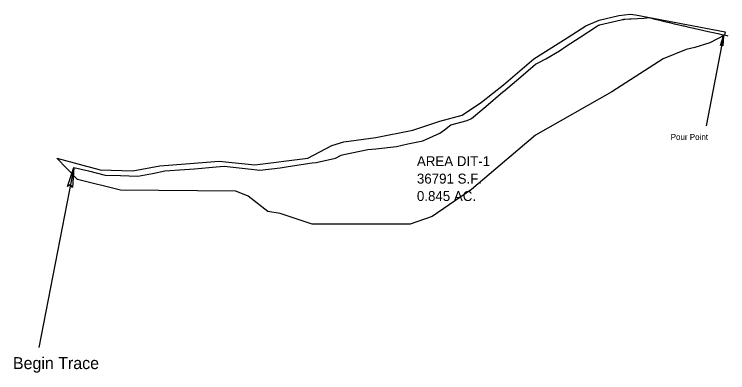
# Model space of a CAD drawing. Extents: x 2773 to 5445, y 2717 to 3371.
import ezdxf

# ---------------------------------------------------------------- set-up
doc = ezdxf.new("R2010")
doc.units = 0
for name, color, linetype in [('Default', 7, 'Continuous'), ('DESIGN - SCRATCH - User 1', 7, 'Continuous'), ('SURVEY - CENTERLINE - Preliminary', 7, 'Continuous'), ('SURVEY - CENTERLINE - Preliminary Text', 7, 'Continuous'), ('SURVEY - DRAINAGE - Area Shapes', 7, 'Continuous')]:
    doc.layers.add(name, color=color, linetype=linetype)

msp = doc.modelspace()

# ---------------------------------------------------------------- linework, layer by layer
at = {"layer": 'DESIGN - SCRATCH - User 1'}
msp.add_line((3485.62, 3055.04), (3468.09, 2964.59), dxfattribs=at)
msp.add_lwpolyline([(3485.62, 3055.04), (3484.94, 3044.93), (3483.96, 3046.45), (3482.43, 3045.42)], close=True, dxfattribs=at)
msp.add_lwpolyline([(3485.62, 3055.04), (3484.94, 3044.93), (3483.96, 3046.45), (3482.43, 3045.42), (3485.62, 3055.04)], dxfattribs=at)
at = {"layer": 'SURVEY - CENTERLINE - Preliminary'}
msp.add_lwpolyline([(2832.45, 2922.94), (2847.47, 2919.39), (2864.12, 2915.09), (2879.54, 2914.67), (2897.07, 2914.19), (2911.62, 2916.79), (2923.98, 2919.53), (2943.7, 2920.94), (2954, 2921.66), (2975.77, 2923.4), (2983.69, 2924.13), (3007.85, 2921.56), (3019.5, 2920.26), (3039.93, 2922.51), (3047.96, 2924), (3072.01, 2927.46), (3076.15, 2928.03), (3095.68, 2932.32), (3101.29, 2935.2), (3104.08, 2936.04), (3127.95, 2940.82), (3136.16, 2941.67), (3156.99, 2943.95), (3168.24, 2946.59), (3183.5, 2949.72), (3200.31, 2957.37), (3205.01, 2960.65), (3211.67, 2965.51), (3228.11, 2969.93), (3232.39, 2972.04), (3246.55, 2984.04), (3263.83, 2998.69), (3264.21, 2998.96), (3264.47, 2999.15), (3281.86, 3013.89), (3296.54, 3026.47), (3300.1, 3028.21), (3306.96, 3031.88), (3320.74, 3040.03), (3328.62, 3045.44), (3340.44, 3052.84), (3359.01, 3065.07), (3360.01, 3065.56), (3360.12, 3065.6), (3360.17, 3065.62), (3360.25, 3065.64), (3360.4, 3065.7), (3360.57, 3065.75), (3360.7, 3065.79), (3360.78, 3065.82), (3360.8, 3065.82), (3361.06, 3065.89), (3382.86, 3070.98), (3384.05, 3071.26), (3385.06, 3071.46), (3385.52, 3071.55), (3386.45, 3071.61), (3391.06, 3071.91), (3392.78, 3072.02), (3405.45, 3072.83), (3407.45, 3072.97), (3408.47, 3073.05), (3408.53, 3073.1), (3408.53, 3073.1), (3408.54, 3073.11), (3408.79, 3073.22), (3408.84, 3073.27), (3409.89, 3073.25), (3409.92, 3073.26), (3411.8, 3072.89), (3416.67, 3071.74), (3421.55, 3070.6), (3424.85, 3069.83), (3426.42, 3069.46), (3431.1, 3068.37), (3431.29, 3068.32), (3436.16, 3067.18), (3441.04, 3066.03), (3445.15, 3065.07), (3445.91, 3064.89), (3450.78, 3063.76), (3455.66, 3062.63), (3456.93, 3062.35), (3460.27, 3061.61), (3470.31, 3059.38), (3475.19, 3058.28), (3480.07, 3057.19), (3484.95, 3056.09), (3486.24, 3055.83), (3489.01, 3055.29), (3489.86, 3055.12)], dxfattribs=at)
at = {"layer": 'SURVEY - CENTERLINE - Preliminary Text'}
msp.add_line((2832.45, 2922.94), (2797.38, 2742.04), dxfattribs=at)
msp.add_lwpolyline([(2832.45, 2922.94), (2831.08, 2902.73), (2829.12, 2905.76), (2826.07, 2903.7)], close=True, dxfattribs=at)
msp.add_lwpolyline([(2832.45, 2922.94), (2831.08, 2902.73), (2829.12, 2905.76), (2826.07, 2903.7), (2832.45, 2922.94)], dxfattribs=at)
at = {"layer": 'SURVEY - DRAINAGE - Area Shapes'}
for points in [[(3328.62, 3053.06), (3347.21, 3065.07), (3360.7, 3070.87), (3380.24, 3075.46), (3391.7, 3076.61), (3397.13, 3076.03), (3487.12, 3058.96)], [(3487.12, 3058.96), (3486.62, 3055.76), (3471.95, 3048.08), (3456.93, 3043.22), (3448, 3041.12), (3424.81, 3031.88), (3373.51, 2998.69), (3296.54, 2955.27), (3232.39, 2900.73), (3192.87, 2873.65), (3170.72, 2865.94), (3072.01, 2865.94), (3039.93, 2876.62), (3027.7, 2878.6), (3007.85, 2894.22), (2995.32, 2899.13)], [(2815.39, 2932.32), (2858.99, 2920.4), (2891.93, 2919.5), (2919.02, 2924.66), (2949.04, 2926.79), (2978.78, 2929.2), (3014.57, 2925.37), (3067.83, 2932.32), (3091.99, 2944.83), (3104.08, 2948.44), (3136.16, 2953.1), (3173.27, 2960.3), (3200.31, 2969.24), (3222.91, 2975.32), (3242.33, 2988.41), (3264.47, 3005.79), (3295.08, 3031.88), (3328.62, 3053.06)], [(2995.32, 2899.13), (2879.54, 2900.02), (2836.23, 2910.76), (2815.39, 2932.32)]]:
    msp.add_lwpolyline(points, dxfattribs=at)

# ---------------------------------------------------------------- texts
at = {"layer": 'Default'}
for s, p in [('AREA DIT-1', (3177.43, 2924.21)), ('36791 S.F.', (3177.43, 2906.71)), ('0.845 AC.', (3177.43, 2889.21))]:
    msp.add_text(s, height=10, dxfattribs=at).set_placement(p)
at = {"layer": 'DESIGN - SCRATCH - User 1'}
msp.add_text('Pour Point', height=6, dxfattribs=at).set_placement((3432.55, 2950.53))
at = {"layer": 'SURVEY - CENTERLINE - Preliminary Text'}
msp.add_text('Begin Trace ', height=12, dxfattribs=at).set_placement((2771.39, 2720.52))

doc.saveas('drawing.dxf')
